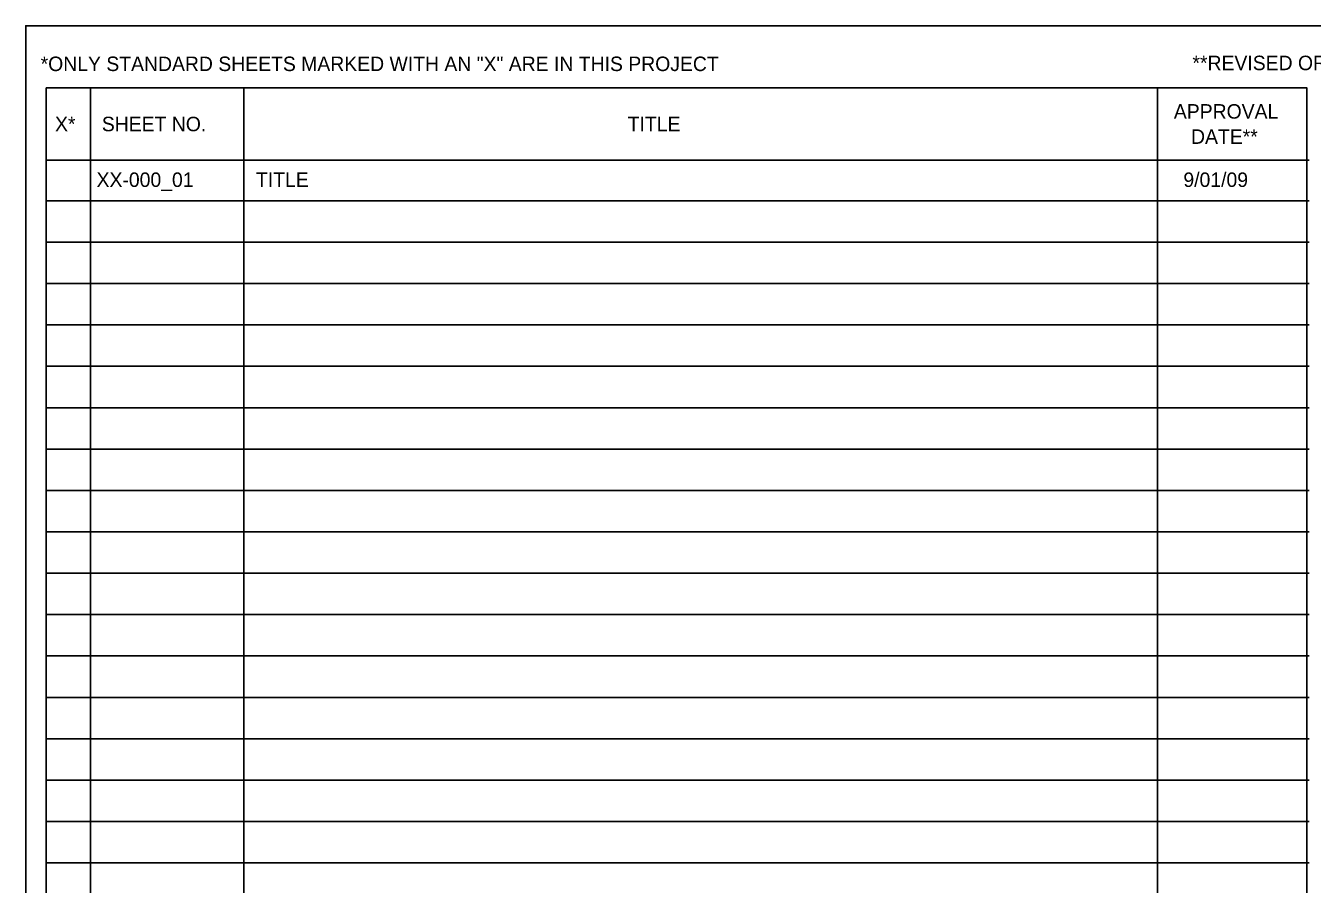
# Model space of a CAD drawing. Extents: x 0 to 5.28, y 0 to 1.73.
# Drawn here: x 0 to 1.295, y 0.865 to 1.729 of the extents above; entities that cross this region are included whole.
import ezdxf

# ---------------------------------------------------------------- set-up
doc = ezdxf.new("R2010")
doc.units = 0
for name, color, linetype in [('CT_Border_Perimeter_Shape', 7, 'Continuous'), ('CT_Dimensions', 7, 'Continuous'), ('CT_List_of _Standards', 7, 'Continuous')]:
    doc.layers.add(name, color=color, linetype=linetype)

msp = doc.modelspace()

# ---------------------------------------------------------------- linework, layer by layer
at = {"layer": 'CT_Border_Perimeter_Shape'}
msp.add_lwpolyline([(0, 0), (2.6458, 0), (2.6458, 1.7292), (0, 1.7292)], close=True, dxfattribs=at)
at = {"layer": 'CT_Dimensions'}
msp.add_lwpolyline([(0.0204, 1.6667), (1.2892, 1.6667), (1.2892, 0.2187), (0.0204, 0.2187)], close=True, dxfattribs=at)
msp.add_lwpolyline([(0.0204, 1.6667), (1.2892, 1.6667), (1.2892, 0.2187), (0.0204, 0.2187)], close=True, dxfattribs=at)
at = {"layer": 'CT_List_of _Standards'}
for p, q in [((0.0651, 1.6667), (0.0651, 0.2187)), ((0.2196, 1.6667), (0.2196, 0.2187)), ((1.1388, 1.6667), (1.1388, 0.2187)), ((0.0204, 1.5937), (1.2917, 1.5937)), ((0.0204, 1.5528), (1.2917, 1.5528)), ((0.0204, 1.5528), (1.2917, 1.5528)), ((0.0204, 1.5112), (1.2917, 1.5112)), ((0.0204, 1.5112), (1.2917, 1.5112)), ((0.0204, 1.4695), (1.2917, 1.4695)), ((0.0204, 1.4695), (1.2917, 1.4695)), ((0.0204, 1.4278), (1.2917, 1.4278)), ((0.0204, 1.4278), (1.2917, 1.4278)), ((0.0204, 1.3862), (1.2917, 1.3862)), ((0.0204, 1.3862), (1.2917, 1.3862)), ((0.0204, 1.3445), (1.2917, 1.3445)), ((0.0204, 1.3445), (1.2917, 1.3445)), ((0.0204, 1.3028), (1.2917, 1.3028)), ((0.0204, 1.3028), (1.2917, 1.3028)), ((0.0204, 1.2612), (1.2917, 1.2612)), ((0.0204, 1.2612), (1.2917, 1.2612)), ((0.0204, 1.2195), (1.2917, 1.2195)), ((0.0204, 1.2195), (1.2917, 1.2195)), ((0.0204, 1.1778), (1.2917, 1.1778)), ((0.0204, 1.1778), (1.2917, 1.1778)), ((0.0204, 1.1362), (1.2917, 1.1362)), ((0.0204, 1.1362), (1.2917, 1.1362)), ((0.0204, 1.0945), (1.2917, 1.0945)), ((0.0204, 1.0945), (1.2917, 1.0945)), ((0.0204, 1.0528), (1.2917, 1.0528)), ((0.0204, 1.0528), (1.2917, 1.0528)), ((0.0204, 1.0112), (1.2917, 1.0112)), ((0.0204, 1.0112), (1.2917, 1.0112)), ((0.0204, 0.9695), (1.2917, 0.9695)), ((0.0204, 0.9695), (1.2917, 0.9695)), ((0.0204, 0.9278), (1.2917, 0.9278)), ((0.0204, 0.9278), (1.2917, 0.9278)), ((0.0204, 0.8862), (1.2917, 0.8862)), ((0.0204, 0.8862), (1.2917, 0.8862))]:
    msp.add_line(p, q, dxfattribs=at)

# ---------------------------------------------------------------- texts
at = {"layer": 'CT_Dimensions'}
for s, p in [('*ONLY STANDARD SHEETS MARKED WITH AN "X" ARE IN THIS PROJECT', (0.015, 1.6835)), ('**REVISED OR ADDED', (1.1741, 1.6844))]:
    msp.add_text(s, height=0.014583, dxfattribs=at).set_placement(p)
at = {"layer": 'CT_List_of _Standards'}
for s, p in [('APPROVAL', (1.1554, 1.6356)), ('X*', (0.0295, 1.6229)), ('SHEET NO.', (0.0766, 1.6229)), ('TITLE', (0.6058, 1.6229)), ('DATE**', (1.1727, 1.6102)), ('XX-000_01', (0.0713, 1.5668)), ('TITLE', (0.2317, 1.5668)), ('9/01/09', (1.165, 1.5668))]:
    msp.add_text(s, height=0.01458, dxfattribs=at).set_placement(p)

doc.saveas('drawing.dxf')
